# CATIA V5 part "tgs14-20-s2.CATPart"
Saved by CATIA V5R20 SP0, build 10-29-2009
Part number: TGS14-20-S2
Revision: 1
Definition: design
Nomenclature: TGS14-20-S2
Source: made
Description: NOT SPECIFIED
Bounding box of the stored display mesh (mm): x -22 to 0.8, y 0 to 14, z -6 to 6
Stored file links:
  C:\Users\Raffaele\Desktop\3D X SITO CF\I-MOLD\TGS-S2\tgs14-s2.step\tgs14-20-s2.CATPart
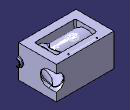
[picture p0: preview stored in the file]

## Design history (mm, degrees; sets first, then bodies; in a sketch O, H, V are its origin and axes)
Set1
  Line1 "LINE #4105": stored without definition
  DatumCurve1 "COMPOSITE_CURVE #4158"
  DatumCurve2 "COMPOSITE_CURVE #4209"
  DatumCurve3 "COMPOSITE_CURVE #4288"
  DatumCurve4 "COMPOSITE_CURVE #4331"
  DatumCurve5 "COMPOSITE_CURVE #4560"
  DatumCurve6 "COMPOSITE_CURVE #4701"
  DatumCurve7 "COMPOSITE_CURVE #4728"
  DatumCurve8 "COMPOSITE_CURVE #4786"
  DatumCurve9 "COMPOSITE_CURVE #4841"
  DatumCurve10 "COMPOSITE_CURVE #4870"
  DatumSurface1 "OPEN_SHELL #4095"
Body1 "MANIFOLD_SOLID_BREP #4096" (main body)
  Solid1: solid without history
